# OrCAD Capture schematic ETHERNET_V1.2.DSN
size B; title: Ethernet; rev: 1.2; company: nuvoTon Technology Corp.; note: Ethernet
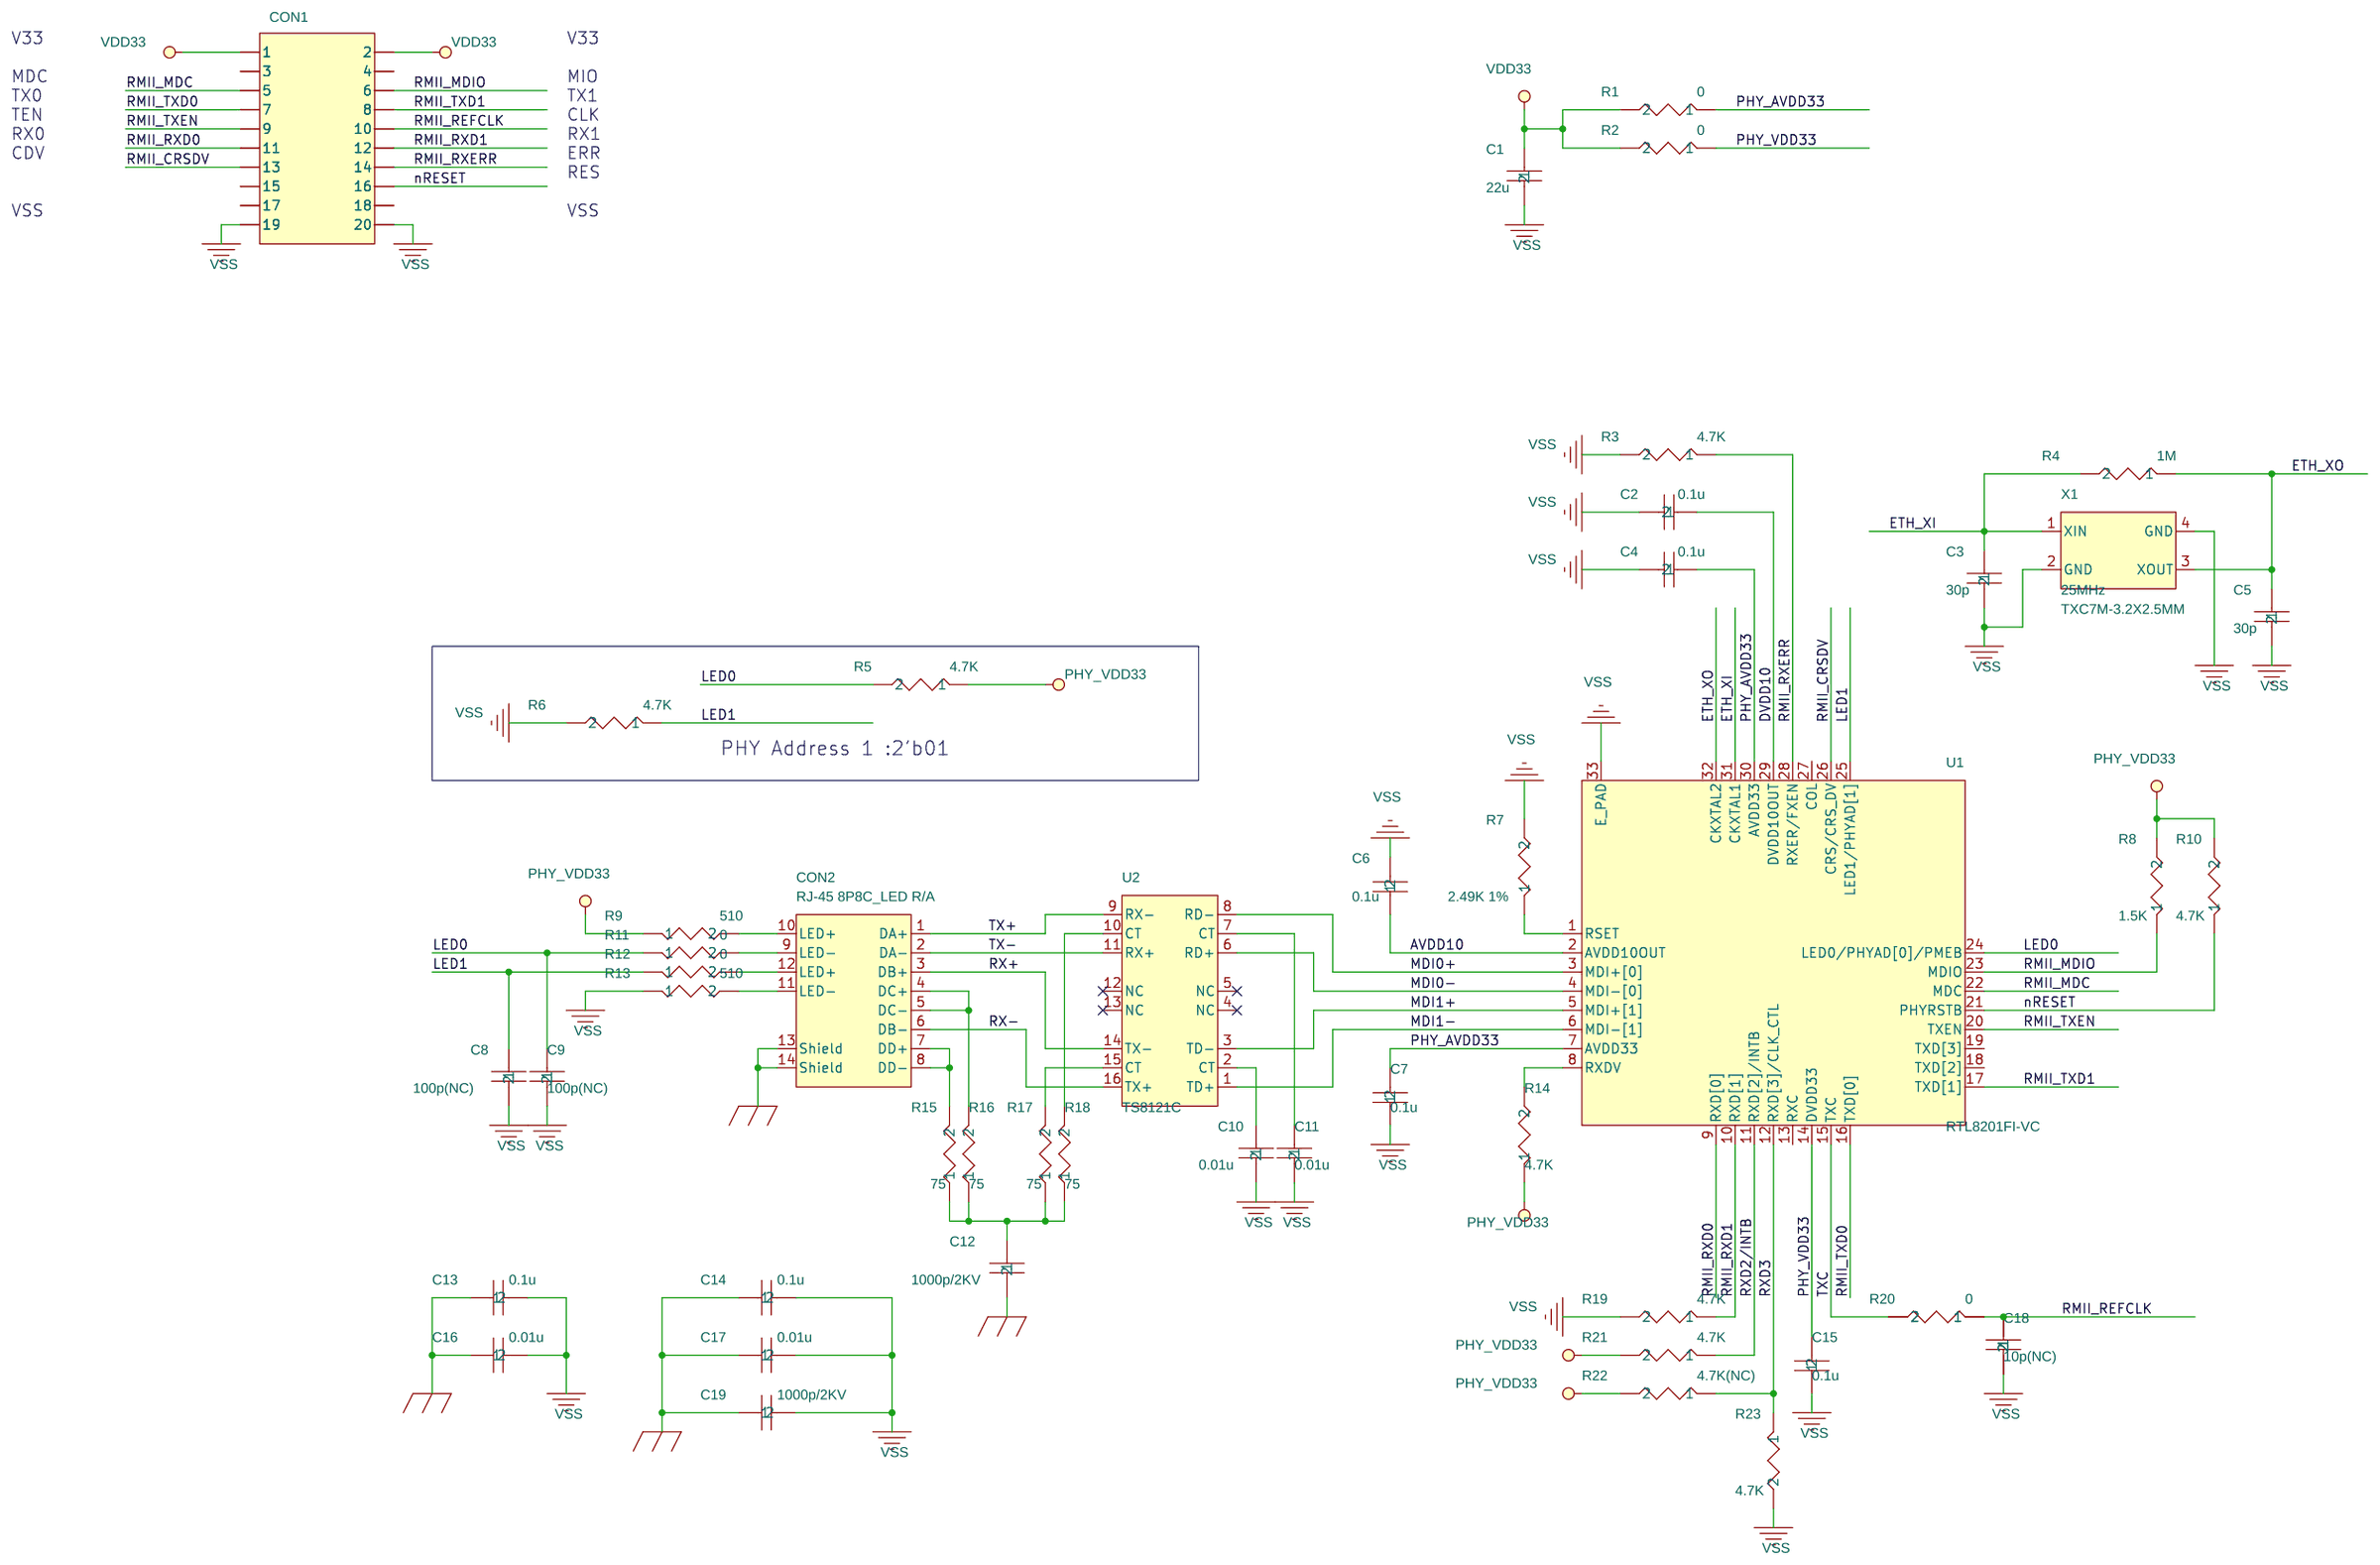
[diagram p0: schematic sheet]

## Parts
C1  22u  [C0603]
C2  0.1u  [C0603]
C3  30p  [C0603]
C4  0.1u  [C0603]
C5  30p  [C0603]
C6  0.1u  [C0603]
C7  0.1u  [C0603]
C8  100p(NC)  [C0603]
C9  100p(NC)  [C0603]
C10  0.01u  [C0603]
C11  0.01u  [C0603]
C12  1000p/2KV  [C1206]
C13  0.1u  [C0603]
C14  0.1u  [C0603]
C15  0.1u  [C0603]
C16  0.01u  [C0603]
C17  0.01u  [C0603]
C18  10p(NC)  [C0603]
C19  1000p/2KV  [C1206]
CON1  RMII_PF  [FEMALE_2x10_2.54mm]
CON2  RJ-45 8P8C_LED R/A  [RJ45\8P\JA\LED]
R1  0  [R0603]
R2  0  [R0603]
R3  4.7K  [R0603]
R4  1M  [R0603]
R5  4.7K  [R0603]
R6  4.7K  [R0603]
R7  2.49K 1%  [R0603]
R8  1.5K  [R0603]
R9  510  [R0603]
R10  4.7K  [R0603]
R11  0  [R0603]
R12  0  [R0603]
R13  510  [R0603]
R14  4.7K  [R0603]
R15  75  [R0603]
R16  75  [R0603]
R17  75  [R0603]
R18  75  [R0603]
R19  4.7K  [R0603]
R20  0  [R0603]
R21  4.7K  [R0603]
R22  4.7K(NC)  [R0603]
R23  4.7K  [R0603]
U1  RTL8201FI-VC  [32-Pin QFN]
U2  TS8121C  [ST6200T]
X1  25MHz  [TXC7M-3.2X2.5MM]

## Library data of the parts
C1 = CAP_NP_1
C2 = CAP_NP_8
C3 = CAP_NP_7
C4 = CAP_NP_13
C5 = CAP_NP_5
C6 = CAP_NP_3
C7 = CAP_NP_2
C8 = CAP_NP_4
C9 = CAP_NP_12
C10 = CAP_NP_10
C11 = CAP_NP
C12 = CAP_NP_14
C13 = CAP_NP_17
C14 = CAP_NP_18
C15 = CAP_NP_9
C16 = CAP_NP_11
C17 = CAP_NP_16
C18 = CAP_NP_15
C19 = CAP_NP_6
CON1 = CON20A
CON2 = RJ45_SHLD_2
R1 = R_9
R2 = R_8
R3 = R_10
R4 = R_2
R5 = R_3
R6 = R_16
R7 = R_7
R8 = R_1
R9 = R_21
R10 = R_11
R11 = R_6
R12 = R_4
R13 = R_22
R14 = R_19
R15 = R_13
R16 = R
R17 = R_15
R18 = R_17
R19 = R_20
R20 = R_12
R21 = R_14
R22 = R_18
R23 = R_5
U1 = RTL8201FI-VC
U2 = PE-68515_0
X1 = Crystal_SMD_2: Vendor: Aurum

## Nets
AVDD10: C6.1 U1.2(AVDD10OUT)
DVDD10: C2.1 U1.29(DVDD10OUT)
GND_EARTH: C12.2 C13.1 C14.1 C16.1 C17.1 C19.1 CON2.13(Shield) CON2.14(Shield)
VDD33: C1.1 CON1.1 CON1.2 R1.2 R2.2
VSS: C1.2 C2.2 C3.2 C4.2 C5.2 C6.2 C7.1 C8.2 C9.2 C10.2 C11.2 C13.2 C14.2 C15.1 C16.2 C17.2 C18.2 C19.2 CON1.19 CON1.20 R3.2 R6.2 R7.2 R13.1 R19.2 R23.2 U1.33(E_PAD) X1.2(GND) X1.4(GND)
ETH_XI: C3.1 R4.2 U1.31(CKXTAL1) X1.1(XIN)
ETH_XO: C5.1 R4.1 U1.32(CKXTAL2) X1.3(XOUT)
LED0: C9.1 R5.2 R11.1 U1.24(LED0/PHYAD[0]/PMEB)
LED1: C8.1 R6.1 R12.1 U1.25(LED1/PHYAD[1])
MDI0+: U1.3(MDI+[0]) U2.8(RD-)
MDI0-: U1.4(MDI-[0]) U2.6(RD+)
MDI1+: U1.5(MDI+[1]) U2.3(TD-)
MDI1-: U1.6(MDI-[1]) U2.1(TD+)
nRESET: CON1.16 R10.1 U1.21(PHYRSTB)
PHY_AVDD33: C4.1 C7.2 R1.1 U1.7(AVDD33) U1.30(AVDD33)
PHY_VDD33: C15.2 R2.1 R5.1 R8.2 R9.1 R10.2 R14.1 R21.2 R22.2 U1.14(DVDD33)
RMII_CRSDV: CON1.13 U1.26(CRS/CRS_DV)
RMII_MDC: CON1.5 U1.22(MDC)
RMII_MDIO: CON1.6 R8.1 U1.23(MDIO)
RMII_REFCLK: C18.1 CON1.10 R20.1
RMII_RXD0: CON1.11 U1.9(RXD[0])
RMII_RXD1: CON1.12 R19.1 U1.10(RXD[1])
RMII_RXERR: CON1.14 R3.1 U1.28(RXER/FXEN)
RMII_TXD0: CON1.7 U1.16(TXD[0])
RMII_TXD1: CON1.8 U1.17(TXD[1])
RMII_TXEN: CON1.9 U1.20(TXEN)
RX+: CON2.3(DB+) U2.14(TX-)
RX-: CON2.6(DB-) U2.16(TX+)
RXD2/INTB: R21.1 U1.11(RXD[2]/INTB)
RXD3: R22.1 R23.1 U1.12(RXD[3]/CLK_CTL)
TX+: CON2.1(DA+) U2.9(RX-)
TX-: CON2.2(DA-) U2.11(RX+)
TXC: R20.2 U1.15(TXC)
N16827669: C11.1 U2.7(CT)
N16827673: R17.2 U2.15(CT)
N16827685: R18.2 U2.10(CT)
N16827687: CON2.7(DD+) CON2.8(DD-) R15.2
N16827695: CON2.4(DC+) CON2.5(DC-) R16.2
N16827762: C10.1 U2.2(CT)
N16827772: C12.1 R15.1 R16.1 R17.1 R18.1
N16827941: CON2.9(LED-) R11.2
N16827954: CON2.12(LED+) R12.2
N16827960: CON2.10(LED+) R9.2
N16827984: CON2.11(LED-) R13.2
N16828080: R7.1 U1.1(RSET)
N16828102: R14.2 U1.8(RXDV)

Not connected (* = marked no-connect by the designer): CON1 3 4 15 17 18; U1 13(RXC) 18(TXD[2]) 19(TXD[3]) 27(COL); U2 4(NC)* 5(NC)* 12(NC)* 13(NC)*

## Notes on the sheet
- V33
- V33
- MDC
- TX0
- MIO
- TX1
- TEN
- CLK
- RX0
- RX1
- CDV
- ERR
- RES
- VSS
- VSS
- PHY Address 1 :2'b01
